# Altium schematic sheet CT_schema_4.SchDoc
size 289 x 230 mm
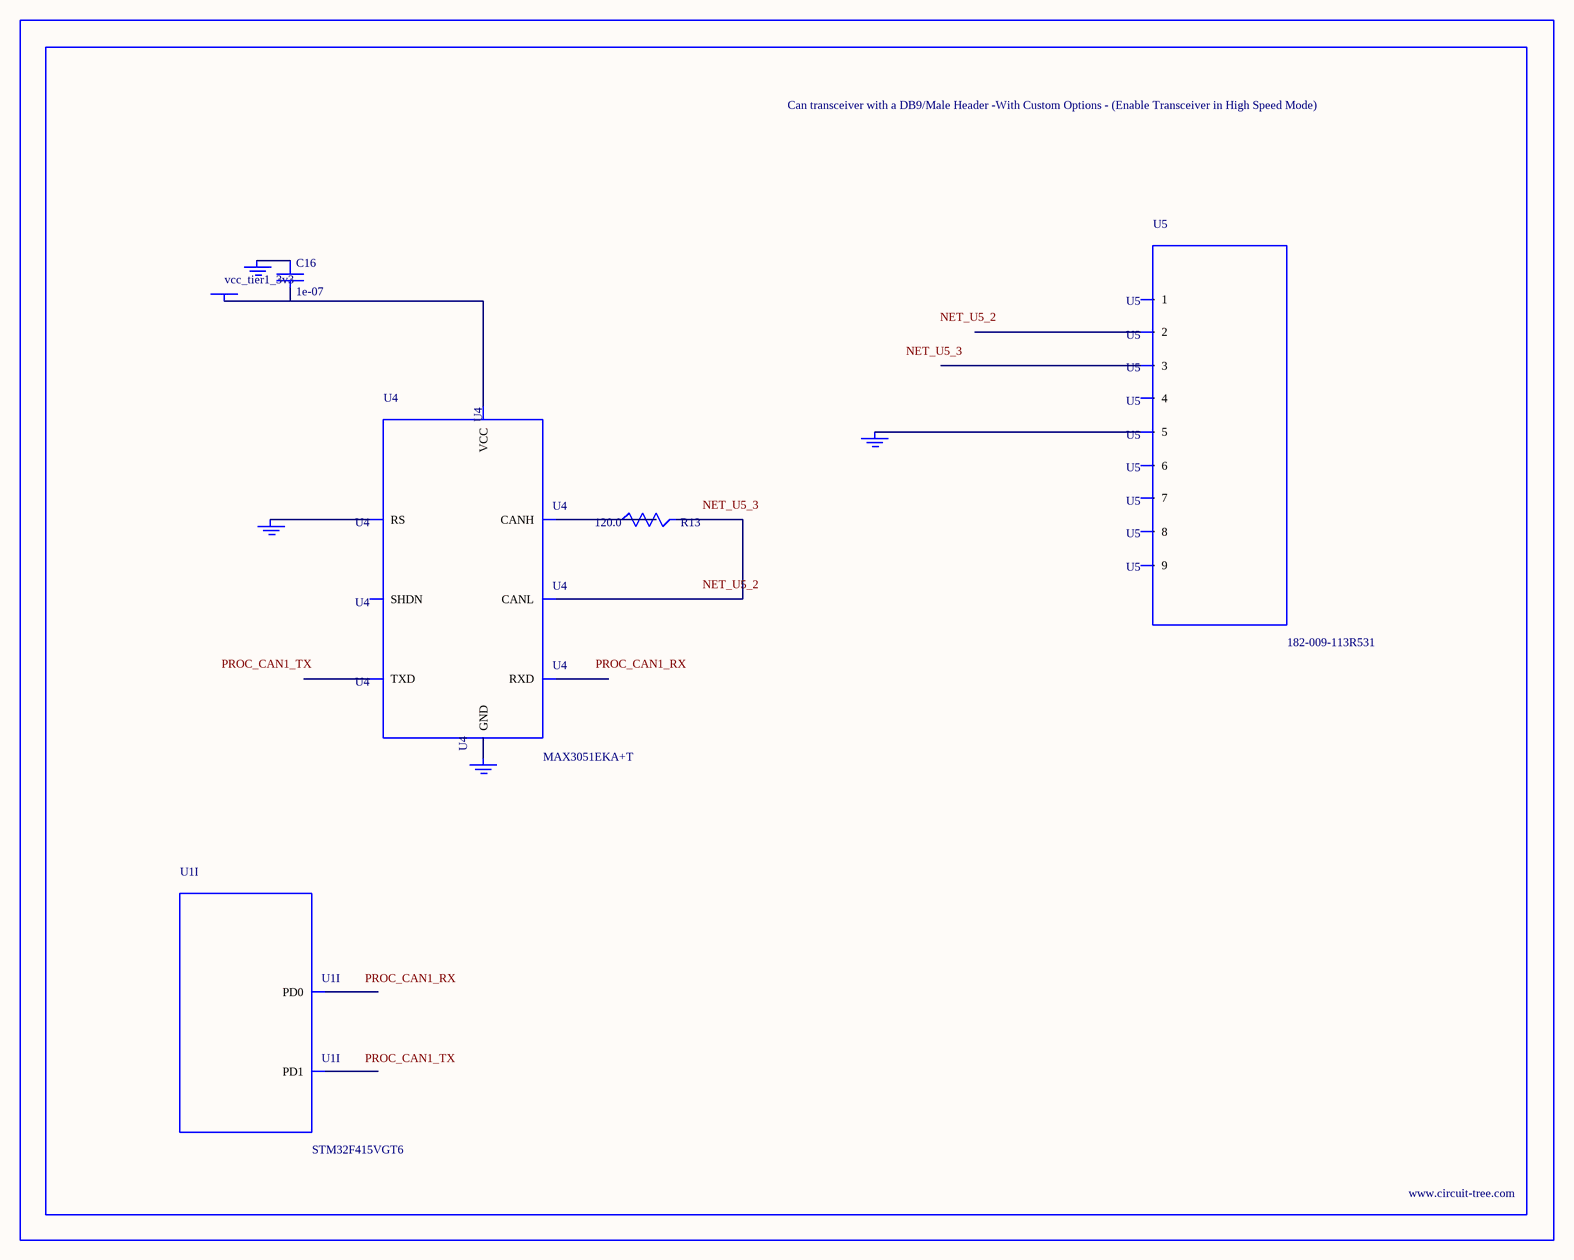
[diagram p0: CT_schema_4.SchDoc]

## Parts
BORDER3  (no value)
C16  1e-07  [C0402]
GND_INSTANCE_3_0  (no value)
GND_INSTANCE_3_1  (no value)
GND_INSTANCE_3_2  (no value)
GND_INSTANCE_3_3  (no value)
POWER_INSTANCE_3_0  vcc_tier1_3v3
R13  120.0  [R0603]
U1  STM32F415VGT6  [LQFP100]  (part I of 11)
U4  MAX3051EKA+T  [SOT-23-8]
U5  182-009-113R531  [182-009-MALE]

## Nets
NetC16_1: C16.1 GND_INSTANCE_3_0.0(GND)
NetC16_2: C16.2 POWER_INSTANCE_3_0.0(PWR) U4.3(VCC)
NetGND_INSTANCE_3_1_0: GND_INSTANCE_3_1.0(GND) U4.8(RS)
NetGND_INSTANCE_3_2_0: GND_INSTANCE_3_2.0(GND) U4.2(GND)
NetGND_INSTANCE_3_3_0: GND_INSTANCE_3_3.0(GND) U5.5
NetR13_1: R13.1 U4.7(CANH)
NetR13_2: R13.2 U4.6(CANL)

Not connected (* = marked no-connect by the designer): U1 81(PD0) 82(PD1); U4 1(TXD) 4(RXD) 5(SHDN); U5 1 2 3 4 6 7 8 9

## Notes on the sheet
- Labels drawn without touching a wire or pin: NET_U5_2, NET_U5_3, PROC_CAN1_RX, PROC_CAN1_TX

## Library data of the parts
BORDER3 = BORDER_PAGE3
C16 = C0402C104K3RACTU
GND_INSTANCE_3_0-GND_INSTANCE_3_3 = GND
POWER_INSTANCE_3_0 = PWR
R13 = RC0603JR-07120RL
